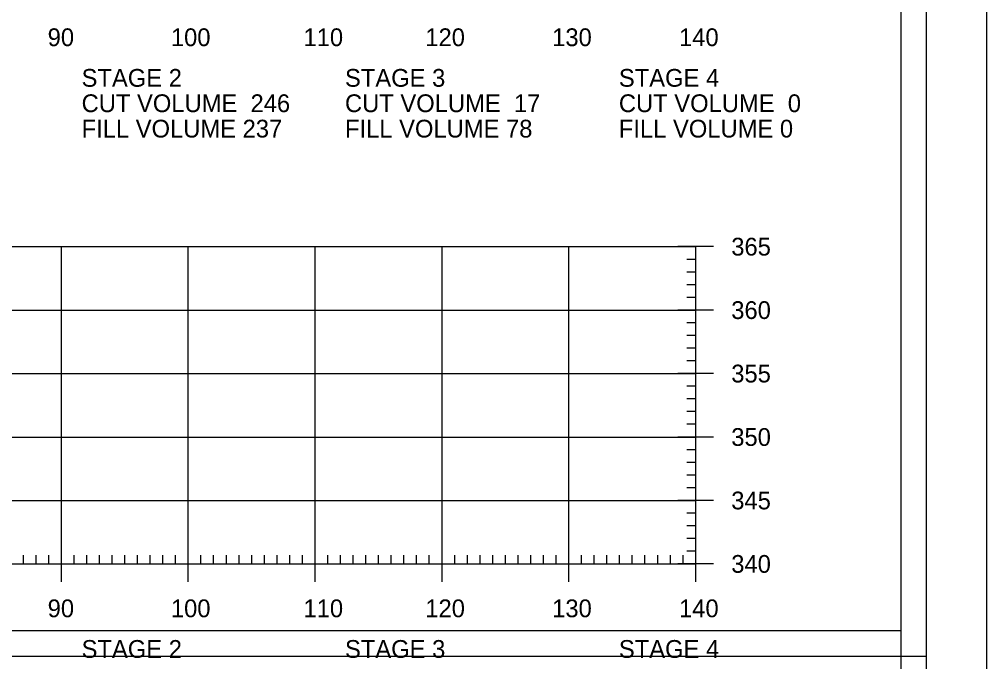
# Model space of a CAD drawing. Extents: x 1368910 to 1369601, y 380116 to 380950.
# Drawn here: x 1369524.3 to 1369600.5, y 380630.1 to 380680.7 of the extents above; entities that cross this region are included whole.
import ezdxf

# ---------------------------------------------------------------- set-up
doc = ezdxf.new("R2010")
doc.units = 0
for name, color, linetype in [('R_Axis', 7, 'Continuous'), ('R_Axis Annot', 7, 'Continuous'), ('R_Border', 7, 'Continuous'), ('R_Border Plan-Plan', 7, 'Continuous'), ('R_Grid', 7, 'Continuous'), ('R_No Plot', 7, 'Continuous')]:
    doc.layers.add(name, color=color, linetype=linetype)

msp = doc.modelspace()

# ---------------------------------------------------------------- linework, layer by layer
at = {"layer": 'R_Axis'}
for p, q in [((1369578.99, 380662.759), (1369576.19, 380662.759)), ((1369577.59, 380637.759), (1369577.59, 380662.759)), ((1369577.59, 380661.759), (1369576.89, 380661.759)), ((1369577.59, 380660.759), (1369576.89, 380660.759)), ((1369577.59, 380659.759), (1369576.89, 380659.759)), ((1369577.59, 380658.759), (1369576.89, 380658.759)), ((1369578.99, 380657.759), (1369576.19, 380657.759)), ((1369577.59, 380656.759), (1369576.89, 380656.759)), ((1369577.59, 380655.759), (1369576.89, 380655.759)), ((1369577.59, 380654.759), (1369576.89, 380654.759)), ((1369577.59, 380653.759), (1369576.89, 380653.759)), ((1369578.99, 380652.759), (1369576.19, 380652.759)), ((1369577.59, 380651.759), (1369576.89, 380651.759)), ((1369577.59, 380650.759), (1369576.89, 380650.759)), ((1369577.59, 380649.759), (1369576.89, 380649.759)), ((1369577.59, 380648.759), (1369576.89, 380648.759)), ((1369578.99, 380647.759), (1369576.19, 380647.759)), ((1369577.59, 380646.759), (1369576.89, 380646.759)), ((1369577.59, 380645.759), (1369576.89, 380645.759)), ((1369577.59, 380644.759), (1369576.89, 380644.759)), ((1369577.59, 380643.759), (1369576.89, 380643.759)), ((1369578.99, 380642.759), (1369576.19, 380642.759)), ((1369577.59, 380641.759), (1369576.89, 380641.759)), ((1369577.59, 380640.759), (1369576.89, 380640.759)), ((1369577.59, 380639.759), (1369576.89, 380639.759)), ((1369527.59, 380636.359), (1369527.59, 380639.159)), ((1369537.59, 380636.359), (1369537.59, 380639.159)), ((1369547.59, 380636.359), (1369547.59, 380639.159)), ((1369557.59, 380636.359), (1369557.59, 380639.159)), ((1369567.59, 380636.359), (1369567.59, 380639.159)), ((1369577.59, 380638.759), (1369576.89, 380638.759)), ((1369577.59, 380636.359), (1369577.59, 380639.159)), ((1369524.59, 380637.759), (1369524.59, 380638.459)), ((1369525.59, 380637.759), (1369525.59, 380638.459)), ((1369526.59, 380637.759), (1369526.59, 380638.459)), ((1369528.59, 380637.759), (1369528.59, 380638.459)), ((1369529.59, 380637.759), (1369529.59, 380638.459)), ((1369530.59, 380637.759), (1369530.59, 380638.459)), ((1369531.59, 380637.759), (1369531.59, 380638.459)), ((1369532.59, 380637.759), (1369532.59, 380638.459)), ((1369533.59, 380637.759), (1369533.59, 380638.459)), ((1369534.59, 380637.759), (1369534.59, 380638.459)), ((1369535.59, 380637.759), (1369535.59, 380638.459)), ((1369536.59, 380637.759), (1369536.59, 380638.459)), ((1369538.59, 380637.759), (1369538.59, 380638.459)), ((1369539.59, 380637.759), (1369539.59, 380638.459)), ((1369540.59, 380637.759), (1369540.59, 380638.459)), ((1369541.59, 380637.759), (1369541.59, 380638.459)), ((1369542.59, 380637.759), (1369542.59, 380638.459)), ((1369543.59, 380637.759), (1369543.59, 380638.459)), ((1369544.59, 380637.759), (1369544.59, 380638.459)), ((1369545.59, 380637.759), (1369545.59, 380638.459)), ((1369546.59, 380637.759), (1369546.59, 380638.459)), ((1369548.59, 380637.759), (1369548.59, 380638.459)), ((1369549.59, 380637.759), (1369549.59, 380638.459)), ((1369550.59, 380637.759), (1369550.59, 380638.459)), ((1369551.59, 380637.759), (1369551.59, 380638.459)), ((1369552.59, 380637.759), (1369552.59, 380638.459)), ((1369553.59, 380637.759), (1369553.59, 380638.459)), ((1369554.59, 380637.759), (1369554.59, 380638.459)), ((1369555.59, 380637.759), (1369555.59, 380638.459)), ((1369556.59, 380637.759), (1369556.59, 380638.459)), ((1369558.59, 380637.759), (1369558.59, 380638.459)), ((1369559.59, 380637.759), (1369559.59, 380638.459)), ((1369560.59, 380637.759), (1369560.59, 380638.459)), ((1369561.59, 380637.759), (1369561.59, 380638.459)), ((1369562.59, 380637.759), (1369562.59, 380638.459)), ((1369563.59, 380637.759), (1369563.59, 380638.459)), ((1369564.59, 380637.759), (1369564.59, 380638.459)), ((1369565.59, 380637.759), (1369565.59, 380638.459)), ((1369566.59, 380637.759), (1369566.59, 380638.459)), ((1369568.59, 380637.759), (1369568.59, 380638.459)), ((1369569.59, 380637.759), (1369569.59, 380638.459)), ((1369570.59, 380637.759), (1369570.59, 380638.459)), ((1369571.59, 380637.759), (1369571.59, 380638.459)), ((1369572.59, 380637.759), (1369572.59, 380638.459)), ((1369573.59, 380637.759), (1369573.59, 380638.459)), ((1369574.59, 380637.759), (1369574.59, 380638.459)), ((1369575.59, 380637.759), (1369575.59, 380638.459)), ((1369576.59, 380637.759), (1369576.59, 380638.459)), ((1369297.59, 380637.759), (1369577.59, 380637.759)), ((1369578.99, 380637.759), (1369576.19, 380637.759))]:
    msp.add_line(p, q, dxfattribs=at)
at = {"layer": 'R_Border'}
msp.add_line((1369595.77, 380527.759), (1369595.77, 380733.219), dxfattribs=at)
at = {"layer": 'R_Border Plan-Plan'}
msp.add_line((1369279.59, 380630.489), (1369595.77, 380630.489), dxfattribs=at)
at = {"layer": 'R_Grid'}
for p, q in [((1369297.59, 380662.759), (1369577.59, 380662.759)), ((1369527.59, 380637.759), (1369527.59, 380662.759)), ((1369537.59, 380637.759), (1369537.59, 380662.759)), ((1369547.59, 380637.759), (1369547.59, 380662.759)), ((1369557.59, 380637.759), (1369557.59, 380662.759)), ((1369567.59, 380637.759), (1369567.59, 380662.759)), ((1369577.59, 380637.759), (1369577.59, 380662.759)), ((1369297.59, 380657.759), (1369577.59, 380657.759)), ((1369297.59, 380652.759), (1369577.59, 380652.759)), ((1369297.59, 380647.759), (1369577.59, 380647.759)), ((1369297.59, 380642.759), (1369577.59, 380642.759)), ((1369297.59, 380637.759), (1369577.59, 380637.759))]:
    msp.add_line(p, q, dxfattribs=at)
at = {"layer": 'R_No Plot'}
for points in [[(1369267.182, 380737.113), (1369600.522, 380737.113), (1369600.522, 380523.776), (1369267.182, 380523.776)], [(1369593.77, 380632.489), (1369281.59, 380632.489), (1369281.59, 380731.219), (1369531.13, 380731.219), (1369531.13, 380721.339), (1369548.67, 380721.339), (1369572.77, 380721.339), (1369572.77, 380699.006), (1369593.77, 380699.006)], [(1369281.59, 380731.219), (1369531.13, 380731.219), (1369531.13, 380721.339), (1369548.67, 380721.339), (1369572.77, 380721.339), (1369572.77, 380699.006), (1369593.77, 380699.006), (1369593.77, 380529.759), (1369281.59, 380529.759)]]:
    msp.add_lwpolyline(points, close=True, dxfattribs=at)

# ---------------------------------------------------------------- texts
at = {"layer": 'R_Axis Annot'}
for s, p in [('90', (1369526.504, 380678.559)), ('100', (1369536.218, 380678.559)), ('110', (1369546.67, 380678.559)), ('120', (1369556.273, 380678.559)), ('130', (1369566.273, 380678.559)), ('140', (1369576.273, 380678.559)), ('STAGE 2', (1369529.18, 380675.359)), ('STAGE 3', (1369549.942, 380675.359)), ('STAGE 4', (1369571.532, 380675.359)), ('CUT VOLUME  246', (1369529.18, 380673.359)), ('CUT VOLUME  17', (1369549.942, 380673.359)), ('CUT VOLUME  0', (1369571.532, 380673.359)), ('FILL VOLUME 237', (1369529.18, 380671.359)), ('FILL VOLUME 78', (1369549.942, 380671.359)), ('FILL VOLUME 0', (1369571.532, 380671.359)), ('365', (1369580.39, 380662.059)), ('360', (1369580.39, 380657.059)), ('355', (1369580.39, 380652.059)), ('350', (1369580.39, 380647.059)), ('345', (1369580.39, 380642.059)), ('340', (1369580.39, 380637.059)), ('90', (1369526.504, 380633.559)), ('100', (1369536.218, 380633.559)), ('110', (1369546.67, 380633.559)), ('120', (1369556.273, 380633.559)), ('130', (1369566.273, 380633.559)), ('140', (1369576.273, 380633.559)), ('STAGE 2', (1369529.18, 380630.359)), ('STAGE 3', (1369549.942, 380630.359)), ('STAGE 4', (1369571.532, 380630.359))]:
    msp.add_text(s, height=1.4, dxfattribs=at).set_placement(p)

doc.saveas('drawing.dxf')
